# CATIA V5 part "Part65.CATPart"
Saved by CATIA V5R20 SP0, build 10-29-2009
Part number: FA 042200-3
Revision: ANY
Definition: UNKNOWN
Nomenclature: FA 042200-3
Source: Unknown
Bounding box of the stored display mesh (mm): x 0 to 2, y -1.45 to 1.45, z -1.45 to 1.45
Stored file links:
  C:\Users\Utente\Desktop\IO LAVORO\3D X SITO CF\CUMSA\3D files FA\FA 042212-21\Part65.CATPart

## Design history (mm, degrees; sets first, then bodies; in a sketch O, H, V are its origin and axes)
Body1 "Revolución1" (main body)
  Solid1: solid without history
